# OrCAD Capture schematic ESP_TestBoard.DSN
size A3; title: ESP_Test Board; rev: 1.0
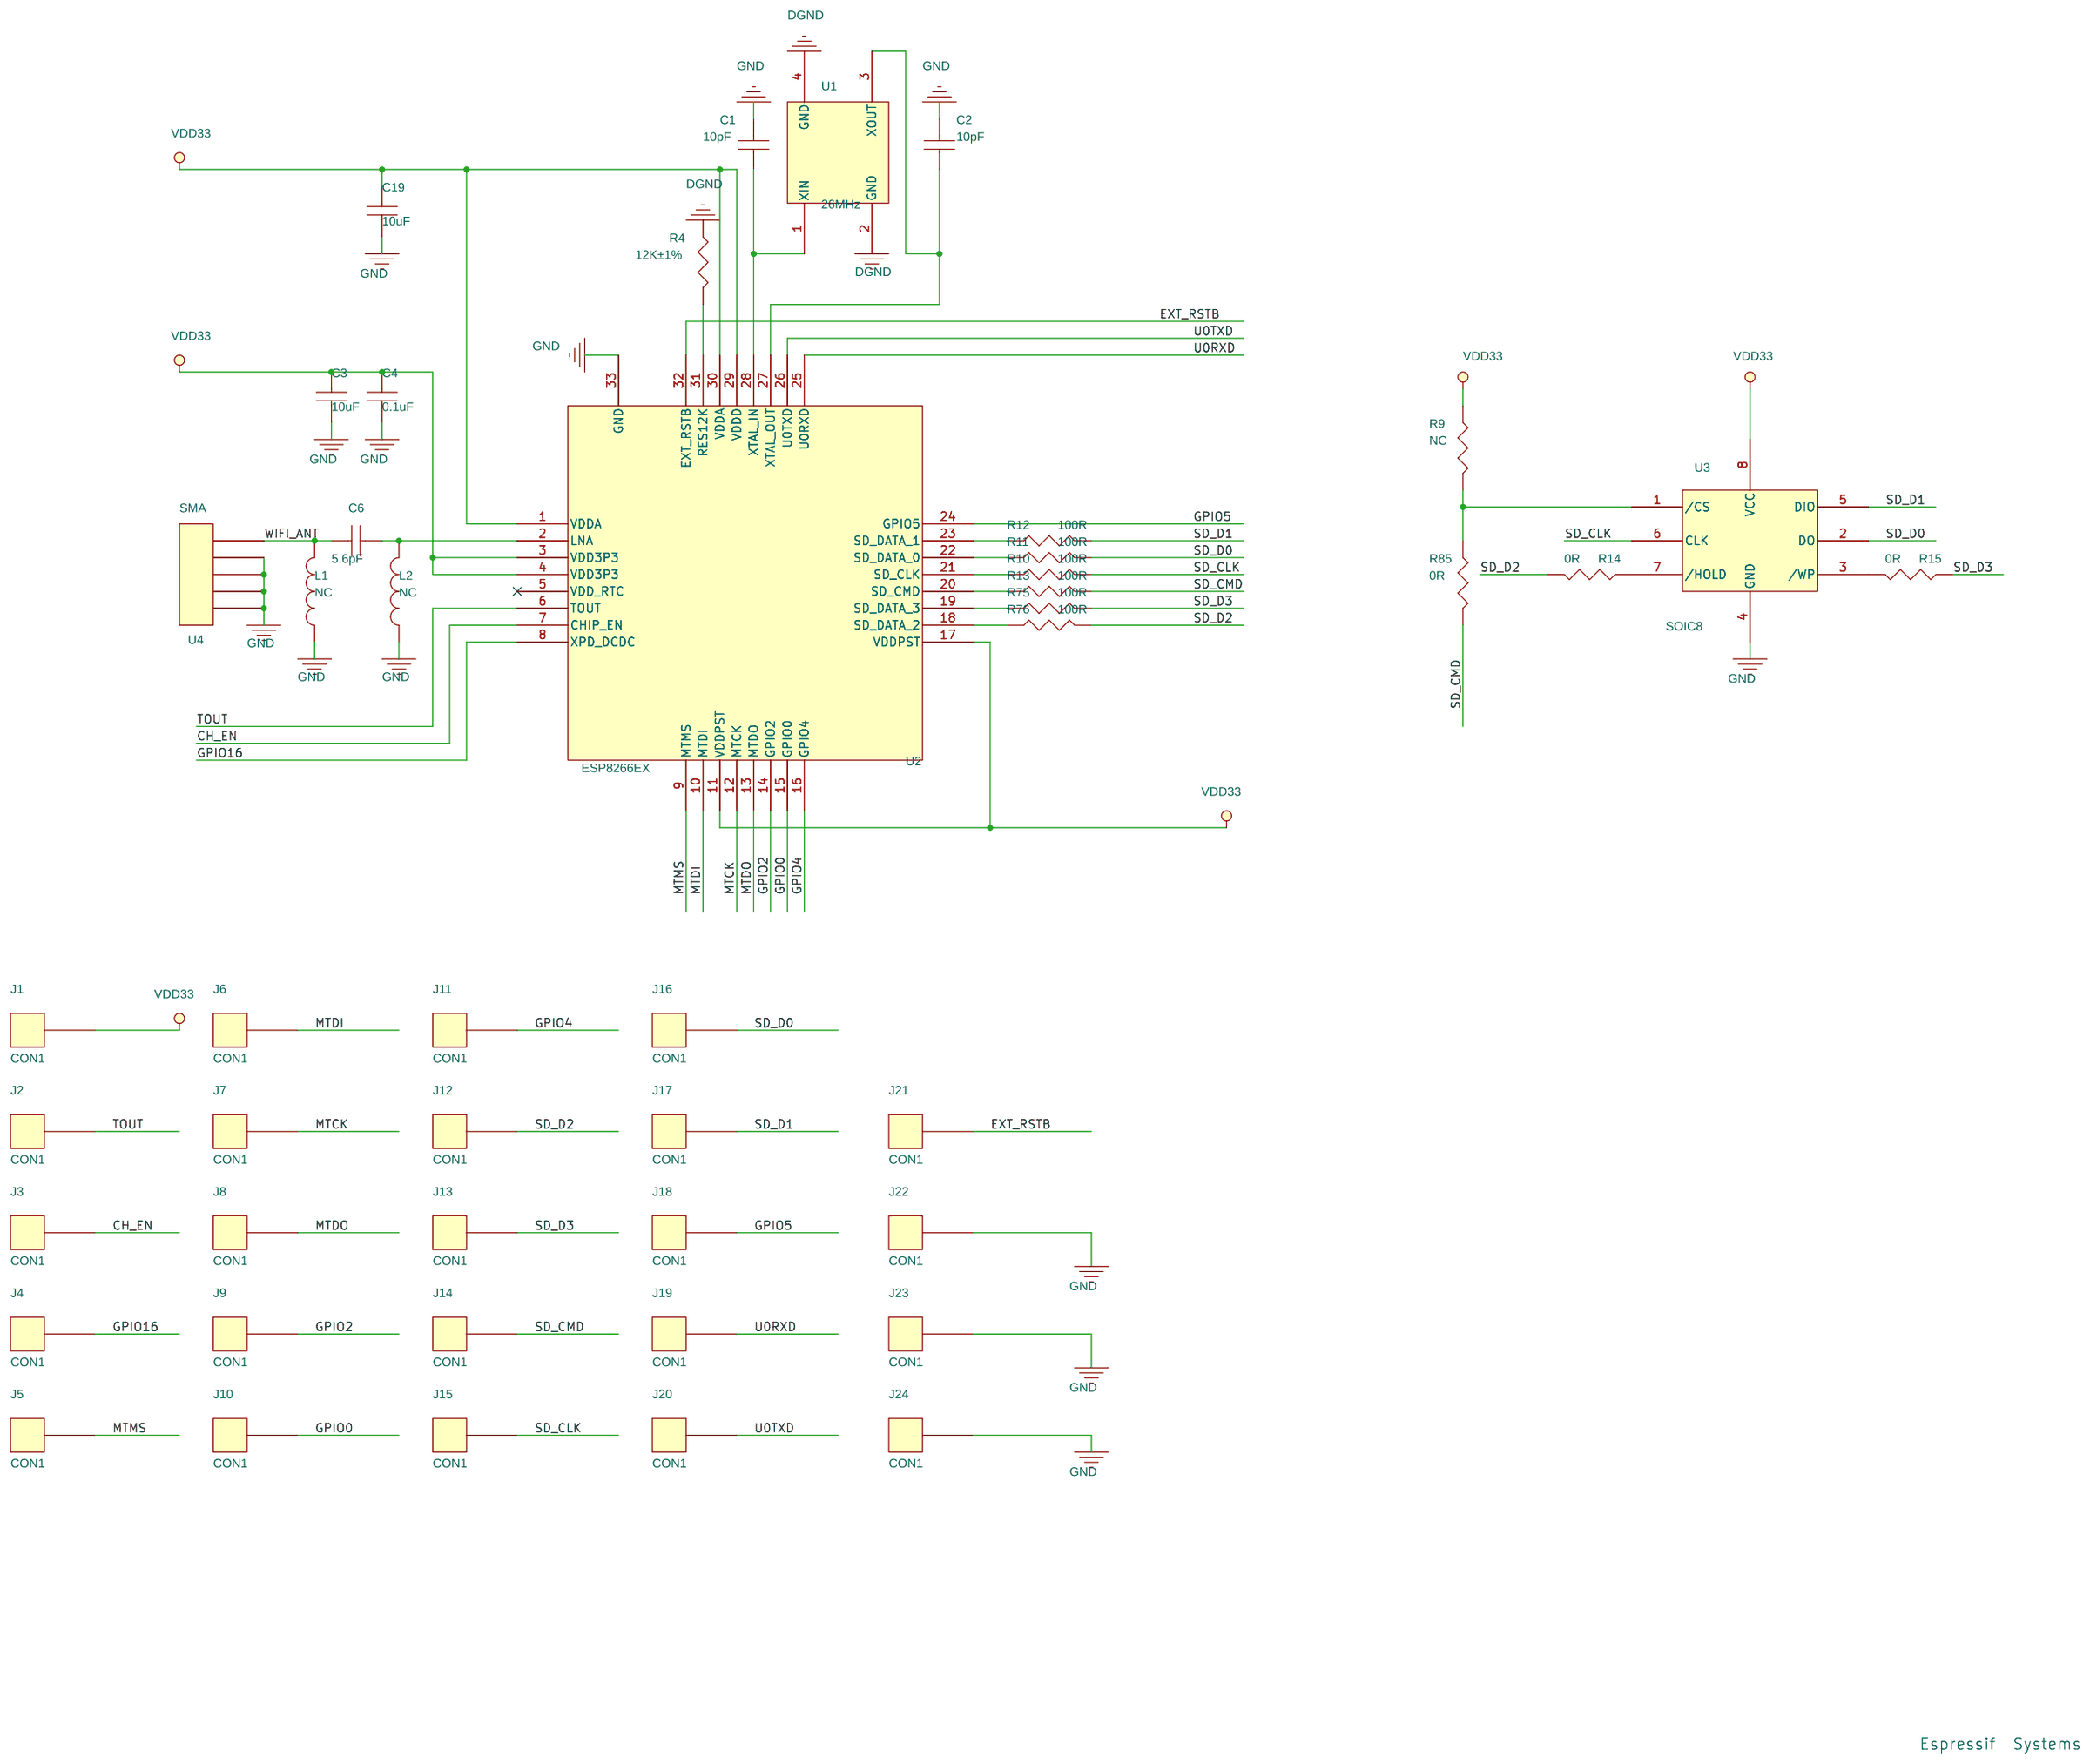
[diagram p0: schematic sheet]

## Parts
C1  10pF  [0402A]
C2  10pF  [0402A]
C3  10uF  [0603C]
C4  0.1uF  [0402A]
C6  5.6pF  [0402A]
C19  10uF  [0603C]
J1  CON1  [1mm_Vias]
J2  CON1  [1mm_Vias]
J3  CON1  [1mm_Vias]
J4  CON1  [1mm_Vias]
J5  CON1  [1mm_Vias]
J6  CON1  [1mm_Vias]
J7  CON1  [1mm_Vias]
J8  CON1  [1mm_Vias]
J9  CON1  [1mm_Vias]
J10  CON1  [1mm_Vias]
J11  CON1  [1mm_Vias]
J12  CON1  [1mm_Vias]
J13  CON1  [1mm_Vias]
J14  CON1  [1mm_Vias]
J15  CON1  [1mm_Vias]
J16  CON1  [1mm_Vias]
J17  CON1  [1mm_Vias]
J18  CON1  [1mm_Vias]
J19  CON1  [1mm_Vias]
J20  CON1  [1mm_Vias]
J21  CON1  [1mm_Vias]
J22  CON1  [1mm_Vias]
J23  CON1  [1mm_Vias]
J24  CON1  [1mm_Vias]
L1  NC  [L0402//A]
L2  NC  [L0402//A]
R4  12K±1%  [0402A]
R9  NC  [0402A]
R10  100R  [0402A]
R11  100R  [0402A]
R12  100R  [0402A]
R13  100R  [0402A]
R14  0R  [0402A]
R15  0R  [0402A]
R75  100R  [0402A]
R76  100R  [0402A]
R85  0R  [0402A]
U1  26MHz  [3225]
U2  ESP8266EX  [QFN32_3.7X3.7]
U3  SOIC8  [SOIC-8P]
U4  SMA  [SMA]

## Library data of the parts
C1-C4 C6 C19 = CAP_NP
J1-J24 = CON1
L1 L2 = INDUCTOR
R4 R9-R15 R75 R76 R85 = RESISTOR_0
U1 = X1_0
U2 = ESP8080_5
U3 = FLASH_0
U4 = CON5_2

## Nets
GND: C1.2 C2.2 C3.2 C4.2 C19.2 J22.1 J23.1 J24.1 L1.1 L2.1 R4.1 U1.2(GND) U1.4(GND) U2.33(GND) U3.4(GND) U4.1 U4.2 U4.3 U4.4
VDD33: C3.1 C4.1 C19.1 J1.1 R9.1 U2.1(VDDA) U2.3(VDD3P3) U2.4(VDD3P3) U2.11(VDDPST) U2.17(VDDPST) U2.29(VDDD) U2.30(VDDA) U3.8(VCC)
CH_EN: J3.1 U2.7(CHIP_EN)
EXT_RSTB: J21.1 U2.32(EXT_RSTB)
GPIO0: J10.1 U2.15(GPIO0)
GPIO2: J9.1 U2.14(GPIO2)
GPIO4: J11.1 U2.16(GPIO4)
GPIO5: J18.1 U2.24(GPIO5)
GPIO16: J4.1 U2.8(XPD_DCDC)
MTCK: J7.1 U2.12(MTCK)
MTDI: J6.1 U2.10(MTDI)
MTDO: J8.1 U2.13(MTDO)
MTMS: J5.1 U2.9(MTMS)
SD_CLK: J15.1 R10.2 U3.6(CLK)
SD_CMD: J14.1 R13.2 R85.2
SD_D0: J16.1 R11.2 U3.2(DO)
SD_D1: J17.1 R12.2 U3.5(DIO)
SD_D2: J12.1 R14.2 R76.2
SD_D3: J13.1 R15.1 R75.2
TOUT: J2.1 U2.6(TOUT)
U0RXD: J19.1 U2.25(U0RXD)
U0TXD: J20.1 U2.26(U0TXD)
WIFI_ANT: C6.1 L1.2 U4.5
N15800555: C6.2 L2.2 U2.2(LNA)
N15800559: C2.1 U1.3(XOUT) U2.27(XTAL_OUT)
N15800563: C1.1 U1.1(XIN) U2.28(XTAL_IN)
N15800567: R4.2 U2.31(RES12K)
N15800675: R12.1 U2.23(SD_DATA_1)
N15800681: R11.1 U2.22(SD_DATA_0)
N15800693: R13.1 U2.20(SD_CMD)
N15800699: R75.1 U2.19(SD_DATA_3)
N15800705: R76.1 U2.18(SD_DATA_2)
N15800827: R10.1 U2.21(SD_CLK)
N15917966: R9.2 R85.1 U3.1(/CS)
N15925706: R14.1 U3.7(/HOLD)
N15925742: R15.2 U3.3(/WP)

Not connected (* = marked no-connect by the designer): U2 5(VDD_RTC)*

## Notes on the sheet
- Espressif  Systems
